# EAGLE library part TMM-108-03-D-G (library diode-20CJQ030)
Samtec TMM Board-Stacker serie. Double Row
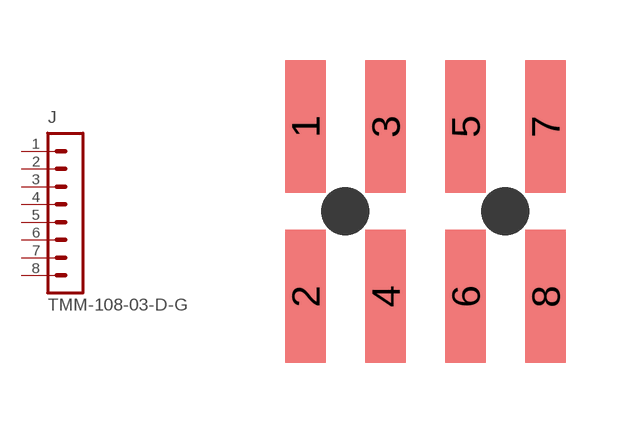
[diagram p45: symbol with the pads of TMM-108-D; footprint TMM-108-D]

Designator prefix J

## TMM-108-03-D-G  [TMM-108-D]
1  1  pas
2  2  pas
3  3  pas
4  4  pas
5  5  pas
6  6  pas
7  7  pas
8  8  pas

## Footprint TMM-108-D (pad centres in mm)
smd 1.02 x 3.32: 1 -3,2.122; 2 -3,-2.122; 3 -1,2.122; 4 -1,-2.122; 5 1,2.122; 6 1,-2.122; 7 3,2.122; 8 3,-2.122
